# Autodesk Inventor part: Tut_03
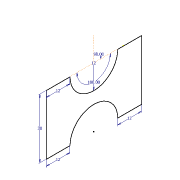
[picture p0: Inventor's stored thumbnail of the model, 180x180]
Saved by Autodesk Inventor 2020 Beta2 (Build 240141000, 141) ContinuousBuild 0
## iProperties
Created: 2019-02
Part Number: Tut_03
Material: Generic
Document SubType Name: Modeling
Designer: LENOVO-CADCIM
Density: 1 g/cm^3
Appearance: Default
Author: LENOVO-CADCIM
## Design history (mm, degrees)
sketch "Sketch1"
  geometry: L1 (0, 15)-(0, 3); L2 (0, 15)-(12, 15); L3 (0, 15)-(0, 27); L4 (0, 27)-(0, 39); L5 (0, 39)-(-30, 39); L6 (-30, 39)-(-30, 27); L7 (-30, 3)-(-30, -9); L8 (-30, -9)-(0, -9); L9 (0, -9)-(0, 3); A1 r 12 centre (0, 15) between (0, 27) and (0, 3); A2 r 12 centre (-30, 15) between (-30, 3) and (-30, 27); 1 further point
  constraints: 18 end point, 5 perpendicular, 5 point on circle, 4 point on line, 2 centre point, 1 horizontal, 1 vertical
  dimensions: "d0" = 12 radius of A1; "d1" = 90 deg angle of L1 L2; "d2" = 180 deg angle of L1 L3; "d3" = 12 distance of L4.start L4.end; "d4" = 30 distance of L4.end L5.end; "d5" = 12 distance of L5.end L6.end; "d6" = 12 distance of L7.start L7.end
